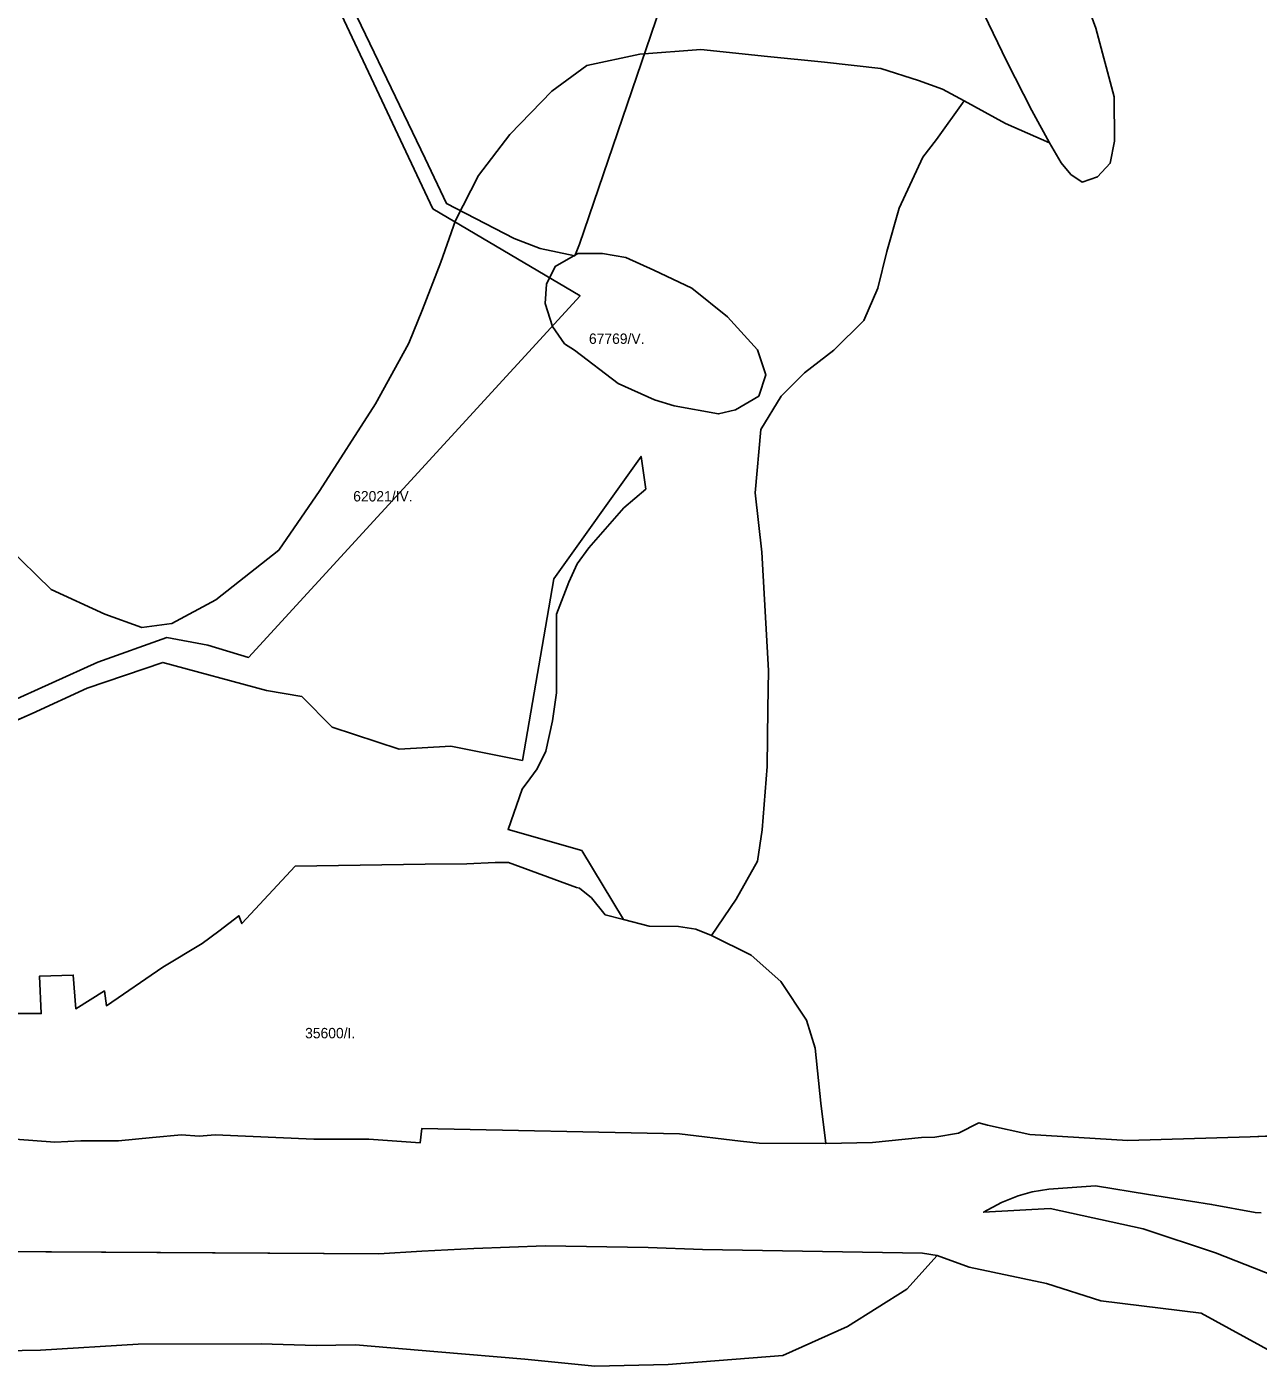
# Model space of a CAD drawing. Extents: x -521621 to -516761, y -1190184 to -1184927.
# Drawn here: x -519264 to -518790, y -1187254 to -1186738 of the extents above; entities that cross this region are included whole.
import ezdxf

# ---------------------------------------------------------------- set-up
doc = ezdxf.new("R2010")
doc.units = 0
doc.layers.add('BPEJ_s', color=7, linetype='Continuous')
doc.layers.add('odvodneni_s', color=7, linetype='Continuous')

msp = doc.modelspace()

# ---------------------------------------------------------------- linework, layer by layer
at = {"layer": 'BPEJ_s'}
for p, q in [((-519061.2, -1186950.69), (-519027.55, -1186903.54)), ((-519027.55, -1186903.54), (-519025.66, -1186916.13)), ((-519025.66, -1186916.13), (-519034.2, -1186923.37)), ((-519034.2, -1186923.37), (-519047.74, -1186938.8)), ((-519047.74, -1186938.8), (-519052.16, -1186944.98)), ((-519052.16, -1186944.98), (-519055.39, -1186952.01)), ((-519073.32, -1187020.75), (-519061.2, -1186950.69)), ((-519055.39, -1186952.01), (-519060.1, -1186964.37)), ((-519060.1, -1186964.37), (-519060.1, -1186994.69)), ((-519241.18, -1186992.83), (-519212.02, -1186982.94)), ((-519212.02, -1186982.94), (-519172.04, -1186993.77)), ((-519262.35, -1187002.71), (-519241.18, -1186992.83)), ((-519172.04, -1186993.77), (-519158.4, -1186996.12)), ((-519158.4, -1186996.12), (-519146.64, -1187007.89)), ((-519060.1, -1186994.69), (-519061.7, -1187005.51)), ((-519303.88, -1187020.75), (-519262.35, -1187002.71)), ((-519146.64, -1187007.89), (-519120.77, -1187016.37)), ((-519061.7, -1187005.51), (-519064.21, -1187017.24)), ((-519120.77, -1187016.37), (-519100.9, -1187015.31)), ((-519100.9, -1187015.31), (-519073.32, -1187020.75)), ((-519064.21, -1187017.24), (-519067.56, -1187023.93)), ((-519067.56, -1187023.93), (-519070.39, -1187027.79)), ((-519070.39, -1187027.79), (-519073.41, -1187031.89)), ((-519073.41, -1187031.89), (-519078.85, -1187047.37)), ((-519078.85, -1187047.37), (-519050.41, -1187055.54)), ((-519050.41, -1187055.54), (-519034.31, -1187082.12)), ((-519160.92, -1187061.56), (-519181.5, -1187083.69)), ((-519110.85, -1187060.77), (-519160.92, -1187061.56)), ((-519094.74, -1187060.56), (-519110.85, -1187060.77)), ((-519083.87, -1187060.14), (-519094.74, -1187060.56)), ((-519078.64, -1187060.14), (-519083.87, -1187060.14)), ((-519052.5, -1187069.77), (-519078.64, -1187060.14)), ((-519051.25, -1187069.98), (-519052.5, -1187069.77)), ((-519046.64, -1187073.75), (-519051.25, -1187069.98)), ((-519041.42, -1187080.23), (-519046.64, -1187073.75)), ((-519182.64, -1187080.64), (-519190.43, -1187086.54)), ((-519181.5, -1187083.69), (-519182.64, -1187080.64)), ((-519034.31, -1187082.12), (-519041.42, -1187080.23)), ((-519190.43, -1187086.54), (-519196.74, -1187091.32)), ((-519196.74, -1187091.32), (-519211.99, -1187100.47)), ((-519211.99, -1187100.47), (-519233.71, -1187115.35)), ((-519246.49, -1187103.52), (-519259.56, -1187103.96)), ((-519259.56, -1187103.96), (-519258.87, -1187118.4)), ((-519245.53, -1187116.5), (-519246.49, -1187103.52)), ((-519234.48, -1187109.63), (-519245.53, -1187116.5)), ((-519233.71, -1187115.35), (-519234.48, -1187109.63)), ((-519258.87, -1187118.4), (-519270.68, -1187118.4)), ((-519112.69, -1187168.17), (-519112.11, -1187162.7)), ((-519112.11, -1187162.7), (-519012.76, -1187164.77)), ((-519012.76, -1187164.77), (-518989.16, -1187167.61)), ((-518914.28, -1187166.02), (-518905.19, -1187164.49)), ((-518905.19, -1187164.49), (-518897.28, -1187160.55)), ((-518897.28, -1187160.55), (-518893.96, -1187161.44)), ((-518893.96, -1187161.44), (-518877.6, -1187164.94)), ((-518877.6, -1187164.94), (-518839.87, -1187167.3)), ((-518792.7, -1187165.88), (-518769.12, -1187164.94)), ((-519268.96, -1187166.85), (-519253.65, -1187167.91)), ((-519253.65, -1187167.91), (-519243.62, -1187167.38)), ((-519243.62, -1187167.38), (-519229.02, -1187167.38)), ((-519229.02, -1187167.38), (-519216.01, -1187166.15)), ((-519216.01, -1187166.15), (-519204.75, -1187165.09)), ((-519204.75, -1187165.09), (-519197.91, -1187165.59)), ((-519197.91, -1187165.59), (-519191.79, -1187165.19)), ((-519191.79, -1187165.19), (-519153.7, -1187166.77)), ((-519153.7, -1187166.77), (-519132.58, -1187166.77)), ((-519132.58, -1187166.77), (-519112.69, -1187168.17)), ((-518989.16, -1187167.61), (-518981.98, -1187168.29)), ((-518981.98, -1187168.29), (-518956.32, -1187168.49)), ((-518956.32, -1187168.49), (-518938.32, -1187168.11)), ((-518938.32, -1187168.11), (-518919.37, -1187166.21)), ((-518919.37, -1187166.21), (-518914.28, -1187166.02)), ((-518839.87, -1187167.3), (-518792.7, -1187165.88)), ((-518852.25, -1187184.81), (-518870.26, -1187186.02)), ((-518831.81, -1187188.13), (-518852.25, -1187184.81)), ((-518882.14, -1187188.59), (-518888.55, -1187191.16)), ((-518876.68, -1187187.14), (-518882.14, -1187188.59)), ((-518870.26, -1187186.02), (-518876.68, -1187187.14)), ((-518807.54, -1187191.97), (-518831.81, -1187188.13)), ((-518888.55, -1187191.16), (-518895.45, -1187195.01)), ((-518895.45, -1187195.01), (-518869.79, -1187193.48)), ((-518869.79, -1187193.48), (-518833.92, -1187201.34)), ((-518790.68, -1187195.03), (-518807.54, -1187191.97)), ((-518788.41, -1187195.16), (-518790.68, -1187195.03)), ((-518833.92, -1187201.34), (-518806.02, -1187210.57)), ((-519128.66, -1187211.03), (-519299.97, -1187210.03)), ((-519112.11, -1187210), (-519128.66, -1187211.03)), ((-519092.1, -1187208.96), (-519112.11, -1187210)), ((-519064.5, -1187207.92), (-519092.1, -1187208.96)), ((-519024.83, -1187208.61), (-519064.5, -1187207.92)), ((-519003.79, -1187209.3), (-519024.83, -1187208.61)), ((-518919.06, -1187210.79), (-519003.79, -1187209.3)), ((-518913.41, -1187211.72), (-518919.06, -1187210.79)), ((-518806.02, -1187210.57), (-518783.14, -1187219.65)), ((-518900.96, -1187216.19), (-518913.41, -1187211.72)), ((-518871.22, -1187222.51), (-518900.96, -1187216.19)), ((-518850.19, -1187229.14), (-518871.22, -1187222.51)), ((-518811.5, -1187233.85), (-518850.19, -1187229.14)), ((-518783.14, -1187249.42), (-518811.5, -1187233.85))]:
    msp.add_line(p, q, dxfattribs=at)
for points in [[(-518897.01, -1186729.33), (-518886.54, -1186751.27), (-518876.79, -1186770.16), (-518869.98, -1186782.55), (-518887, -1186775.12), (-518902.94, -1186766.45), (-518911.3, -1186761.96), (-518920.58, -1186758.55), (-518935.13, -1186753.91), (-518956.79, -1186751.43), (-518978.77, -1186749.34), (-519004.45, -1186746.55), (-519027.98, -1186748.41), (-519048.4, -1186752.74), (-519062.02, -1186762.65), (-519078.11, -1186779.38), (-519090.18, -1186795.17), (-519099.16, -1186812.51), (-519104.73, -1186828.61), (-519111.85, -1186846.89), (-519117.11, -1186859.89), (-519120.83, -1186866.61), (-519129.96, -1186883.29), (-519151.4, -1186916.66), (-519167.28, -1186939.7), (-519191.49, -1186958.76), (-519208.56, -1186967.9), (-519220.08, -1186969.49), (-519234.37, -1186964.32), (-519255.01, -1186954.79), (-519272.08, -1186938.11)], [(-518854.42, -1186732.09), (-518852.18, -1186738.42), (-518845.07, -1186764.9), (-518844.91, -1186781.93), (-518846.61, -1186790.45), (-518851.57, -1186795.71), (-518857.45, -1186797.72), (-518861.78, -1186794.78), (-518865.49, -1186790.29), (-518869.98, -1186782.55), (-518876.79, -1186770.16), (-518886.54, -1186751.27), (-518897.01, -1186729.33)], [(-518769.12, -1187164.94), (-518792.7, -1187165.88), (-518839.87, -1187167.3), (-518877.6, -1187164.94), (-518893.96, -1187161.44), (-518897.28, -1187160.55), (-518905.19, -1187164.49), (-518914.28, -1187166.02), (-518919.37, -1187166.21), (-518938.32, -1187168.11), (-518956.32, -1187168.49), (-518958.16, -1187152.95), (-518960.46, -1187131.7), (-518963.76, -1187120.88), (-518973.66, -1187106.01), (-518985.11, -1187095.79), (-519000.43, -1187088.21), (-518990.84, -1187074.27), (-518982.64, -1187059.56), (-518980.78, -1187047.48), (-518978.89, -1187023.09), (-518978.63, -1187000.91), (-518978.46, -1186986.01), (-518980.93, -1186940.49), (-518983.56, -1186917.57), (-518981.4, -1186893.11), (-518973.51, -1186880.26), (-518964.53, -1186871.28), (-518953.23, -1186862.6), (-518941.63, -1186851.15), (-518936.21, -1186838.6), (-518932.81, -1186824.51), (-518928.01, -1186807.79), (-518918.88, -1186788.12), (-518913.62, -1186781.31), (-518902.94, -1186766.45), (-518887, -1186775.12), (-518869.98, -1186782.55), (-518865.49, -1186790.29), (-518861.78, -1186794.78), (-518857.45, -1186797.72), (-518851.57, -1186795.71), (-518846.61, -1186790.45), (-518844.91, -1186781.93), (-518845.07, -1186764.9), (-518852.18, -1186738.42), (-518854.42, -1186732.09)], [(-519272.08, -1186938.11), (-519255.01, -1186954.79), (-519234.37, -1186964.32), (-519220.08, -1186969.49), (-519208.56, -1186967.9), (-519191.49, -1186958.76), (-519167.28, -1186939.7), (-519151.4, -1186916.66), (-519129.96, -1186883.29), (-519120.83, -1186866.61), (-519117.11, -1186859.89), (-519111.85, -1186846.89), (-519104.73, -1186828.61), (-519099.16, -1186812.51), (-519090.18, -1186795.17), (-519078.11, -1186779.38), (-519062.02, -1186762.65), (-519048.4, -1186752.74), (-519027.98, -1186748.41), (-519004.45, -1186746.55), (-518978.77, -1186749.34), (-518956.79, -1186751.43), (-518935.13, -1186753.91), (-518920.58, -1186758.55), (-518911.3, -1186761.96), (-518902.94, -1186766.45), (-518913.62, -1186781.31), (-518918.88, -1186788.12), (-518928.01, -1186807.79), (-518932.81, -1186824.51), (-518936.21, -1186838.6), (-518941.63, -1186851.15), (-518953.23, -1186862.6), (-518964.53, -1186871.28), (-518973.51, -1186880.26), (-518981.4, -1186893.11), (-518983.56, -1186917.57), (-518980.93, -1186940.49), (-518978.46, -1186986.01), (-518978.63, -1187000.91), (-518978.89, -1187023.09), (-518980.78, -1187047.48), (-518982.64, -1187059.56), (-518990.84, -1187074.27), (-519000.43, -1187088.21), (-519006.47, -1187085.88), (-519013.12, -1187084.8), (-519024.48, -1187084.63), (-519034.31, -1187082.12), (-519050.41, -1187055.54), (-519078.85, -1187047.37), (-519073.41, -1187031.89), (-519070.39, -1187027.79), (-519067.56, -1187023.93), (-519064.21, -1187017.24), (-519061.7, -1187005.51), (-519060.1, -1186994.69), (-519060.1, -1186964.37), (-519055.39, -1186952.01), (-519052.16, -1186944.98), (-519047.74, -1186938.8), (-519034.2, -1186923.37), (-519025.66, -1186916.13), (-519027.55, -1186903.54), (-519061.2, -1186950.69), (-519073.32, -1187020.75), (-519100.9, -1187015.31), (-519120.77, -1187016.37), (-519146.64, -1187007.89), (-519158.4, -1186996.12), (-519172.04, -1186993.77), (-519212.02, -1186982.94), (-519241.18, -1186992.83), (-519262.35, -1187002.71), (-519303.88, -1187020.75)], [(-519270.68, -1187118.4), (-519258.87, -1187118.4), (-519259.56, -1187103.96), (-519246.49, -1187103.52), (-519245.53, -1187116.5), (-519234.48, -1187109.63), (-519233.71, -1187115.35), (-519211.99, -1187100.47), (-519196.74, -1187091.32), (-519190.43, -1187086.54), (-519182.64, -1187080.64), (-519181.5, -1187083.69), (-519160.92, -1187061.56), (-519110.85, -1187060.77), (-519094.74, -1187060.56), (-519083.87, -1187060.14), (-519078.64, -1187060.14), (-519052.5, -1187069.77), (-519051.25, -1187069.98), (-519046.64, -1187073.75), (-519041.42, -1187080.23), (-519034.31, -1187082.12), (-519024.48, -1187084.63), (-519013.12, -1187084.8), (-519006.47, -1187085.88), (-519000.43, -1187088.21), (-518985.11, -1187095.79), (-518973.66, -1187106.01), (-518963.76, -1187120.88), (-518960.46, -1187131.7), (-518958.16, -1187152.95), (-518956.32, -1187168.49), (-518981.98, -1187168.29), (-518989.16, -1187167.61), (-519012.76, -1187164.77), (-519112.11, -1187162.7), (-519112.69, -1187168.17), (-519132.58, -1187166.77), (-519153.7, -1187166.77), (-519191.79, -1187165.19), (-519197.91, -1187165.59), (-519204.75, -1187165.09), (-519216.01, -1187166.15), (-519229.02, -1187167.38), (-519243.62, -1187167.38), (-519253.65, -1187167.91), (-519268.96, -1187166.85)], [(-519850.94, -1187069.23), (-519796.11, -1187106.16), (-519765.16, -1187130.37), (-519705.16, -1187168.1), (-519685.69, -1187175.9), (-519667.22, -1187182.03), (-519652.89, -1187186.47), (-519641.3, -1187189.2), (-519629.99, -1187191.18), (-519601.06, -1187195.24), (-519565.43, -1187200.37), (-519536.97, -1187203.2), (-519506.81, -1187204.71), (-519400, -1187209.9), (-519353.85, -1187209.13), (-519299.97, -1187210.03), (-519128.66, -1187211.03), (-519112.11, -1187210), (-519092.1, -1187208.96), (-519064.5, -1187207.92), (-519024.83, -1187208.61), (-519003.79, -1187209.3), (-518919.06, -1187210.79), (-518913.41, -1187211.72)], [(-518783.14, -1187219.65), (-518806.02, -1187210.57), (-518833.92, -1187201.34), (-518869.79, -1187193.48), (-518895.45, -1187195.01), (-518888.55, -1187191.16), (-518882.14, -1187188.59), (-518876.68, -1187187.14), (-518870.26, -1187186.02), (-518852.25, -1187184.81), (-518831.81, -1187188.13), (-518807.54, -1187191.97), (-518790.68, -1187195.03), (-518788.41, -1187195.16)], [(-519294.6, -1187248.78), (-519259.17, -1187248.17), (-519221.47, -1187245.9), (-519174.09, -1187245.69), (-519152.82, -1187246.42), (-519137.62, -1187246.1), (-519105.9, -1187248.79), (-519072.32, -1187251.67), (-519045.33, -1187254.35), (-519017.1, -1187253.73), (-518972.81, -1187250.23), (-518947.88, -1187239.1), (-518925.02, -1187224.67), (-518913.41, -1187211.72), (-518900.96, -1187216.19), (-518871.22, -1187222.51), (-518850.19, -1187229.14), (-518811.5, -1187233.85), (-518783.14, -1187249.42)], [(-518913.41, -1187211.72), (-518925.02, -1187224.67), (-518947.88, -1187239.1), (-518972.81, -1187250.23), (-519017.1, -1187253.73), (-519045.33, -1187254.35), (-519072.32, -1187251.67), (-519105.9, -1187248.79), (-519137.62, -1187246.1), (-519152.82, -1187246.42), (-519174.09, -1187245.69), (-519221.47, -1187245.9), (-519259.17, -1187248.17), (-519294.6, -1187248.78)]]:
    msp.add_lwpolyline(points, dxfattribs=at)
msp.add_lwpolyline([(-519051.96, -1186825.29), (-519042.37, -1186825.29), (-519033.39, -1186826.83), (-519022.56, -1186831.64), (-519008.01, -1186838.6), (-518994.24, -1186849.75), (-518982.64, -1186862.45), (-518979.39, -1186872.05), (-518982.17, -1186880.26), (-518991.15, -1186885.52), (-518997.72, -1186887.13), (-519014.76, -1186884.01), (-519022.41, -1186881.65), (-519036.33, -1186875.46), (-519053.2, -1186862.6), (-519057.07, -1186860.12), (-519061.71, -1186853.47), (-519064.5, -1186844.49), (-519064.03, -1186837.05), (-519060.63, -1186830.24)], close=True, dxfattribs=at)
msp.add_lwpolyline([(-519051.96, -1186825.29), (-519042.37, -1186825.29), (-519033.39, -1186826.83), (-519022.56, -1186831.64), (-519008.01, -1186838.6), (-518994.24, -1186849.75), (-518982.64, -1186862.45), (-518979.39, -1186872.05), (-518982.17, -1186880.26), (-518991.15, -1186885.52), (-518997.72, -1186887.13), (-519014.76, -1186884.01), (-519022.41, -1186881.65), (-519036.33, -1186875.46), (-519053.2, -1186862.6), (-519057.07, -1186860.12), (-519061.71, -1186853.47), (-519064.5, -1186844.49), (-519064.03, -1186837.05), (-519060.63, -1186830.24)], close=True, dxfattribs=at)
at = {"layer": 'odvodneni_s'}
for points in [[(-519180.32, -1186653.96), (-519107.8, -1186808), (-519051.05, -1186841.62), (-519178.87, -1186981.02), (-519194.65, -1186976.29), (-519210.41, -1186973.39), (-519237.02, -1186982.89), (-519290.02, -1187006.82), (-519321.89, -1187019.12), (-519352.74, -1187018), (-519387.18, -1187008.83), (-519413.12, -1186998.88), (-519431.46, -1186995.3), (-519456.28, -1187004.92), (-519503.72, -1187029.72), (-519516.77, -1187030.92), (-519548.9, -1187029.52), (-519623.6, -1186999.2), (-519652.51, -1186990.16), (-519663.36, -1186986.75), (-519714.16, -1186984.74), (-519763.11, -1186970.98), (-519841.01, -1186940.74)], [(-519003.53, -1186681.39), (-519051.29, -1186821.65), (-519053.15, -1186826.17), (-519066.5, -1186823.31), (-519076.52, -1186819.49), (-519102.52, -1186806.01), (-519110.84, -1186788.68), (-519146.97, -1186713.39)]]:
    msp.add_lwpolyline(points, dxfattribs=at)

# ---------------------------------------------------------------- texts
at = {"layer": 'BPEJ_s'}
for s, p in [('67769/V.', (-519047.64, -1186860.12)), ('62021/IV.', (-519138.56, -1186920.88)), ('35600/I.', (-519157.1, -1187127.9))]:
    msp.add_text(s, height=4, dxfattribs=at).set_placement(p)

doc.saveas('drawing.dxf')
